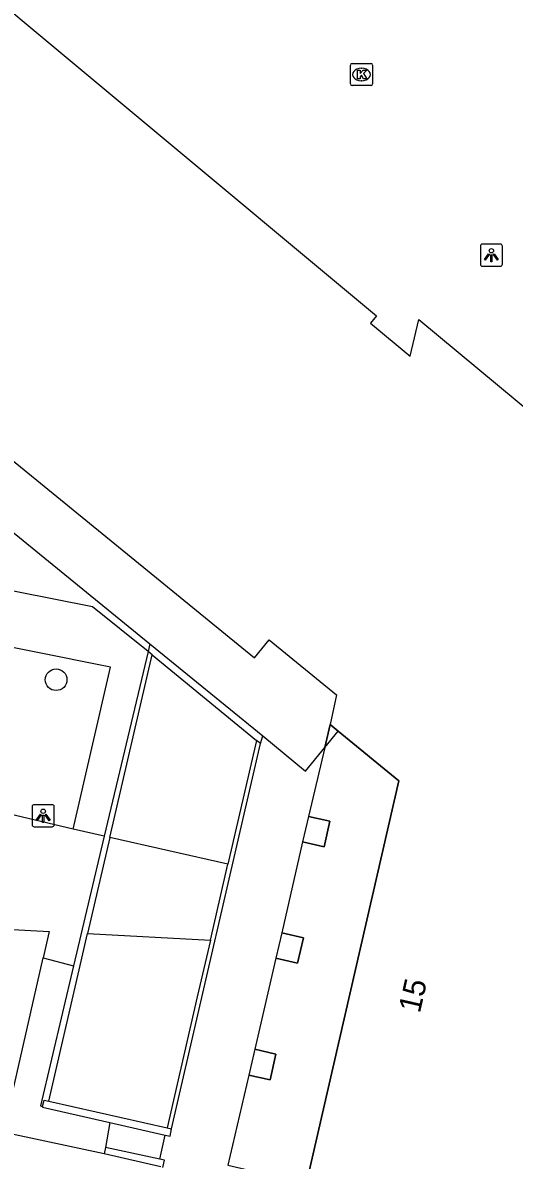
# Model space of a CAD drawing. Extents: x 161772 to 163123, y 383092 to 383917.
# Drawn here: x 161929.2 to 161951.4, y 383180.8 to 383232.1 of the extents above; entities that cross this region are included whole.
import ezdxf

# ---------------------------------------------------------------- set-up
doc = ezdxf.new("R2010")
doc.units = 0
for name, color, linetype in [('IMGEO_Boom', 7, 'Continuous'), ('IMGEO_Kolk', 7, 'Continuous'), ('IMGEO_Lichtpunt', 7, 'Continuous'), ('IMGEO_Pand', 7, 'Continuous'), ('IMGEO_Pand_nummerreeks', 7, 'Continuous'), ('IMGEO_Pand_overbouw', 7, 'Continuous'), ('IMGEO_Voetpad_gesloten', 7, 'Continuous'), ('IMGEO_Voetpad_op_trap', 7, 'Continuous'), ('IMGEO_Voetpad_open', 7, 'Continuous')]:
    doc.layers.add(name, color=color, linetype=linetype)

msp = doc.modelspace()

# ---------------------------------------------------------------- linework, layer by layer
at = {"layer": 'IMGEO_Boom'}
msp.add_circle((161930.751, 383202.465), 0.489, dxfattribs=at)
at = {"layer": 'IMGEO_Kolk'}
for p, q in [((161944.115, 383230.303), (161944.967, 383230.303)), ((161944.04, 383229.377), (161944.04, 383230.229)), ((161944.528, 383230.083), (161944.553, 383230.083)), ((161945.041, 383230.229), (161945.041, 383229.377)), ((161944.967, 383229.303), (161944.115, 383229.303)), ((161944.551, 383229.523), (161944.526, 383229.523))]:
    msp.add_line(p, q, dxfattribs=at)
for points in [[(161944.115, 383230.303), (161944.967, 383230.303)], [(161944.04, 383229.377), (161944.04, 383230.229)], [(161944.361, 383230.003), (161944.484, 383230.003), (161944.484, 383229.852), (161944.614, 383230.003), (161944.778, 383230.003), (161944.632, 383229.852), (161944.785, 383229.603), (161944.633, 383229.603), (161944.548, 383229.767), (161944.484, 383229.7), (161944.484, 383229.603), (161944.361, 383229.603), (161944.361, 383230.003)], [(161945.041, 383230.229), (161945.041, 383229.377)], [(161944.967, 383229.303), (161944.115, 383229.303)]]:
    msp.add_lwpolyline(points, dxfattribs=at)
for centre, start, end in [((161944.117, 383230.227), 91.552, 178.448), ((161944.117, 383230.227), 91.552, 178.448), ((161944.965, 383230.227), 1.552, 88.448), ((161944.965, 383230.227), 1.552, 88.448), ((161944.117, 383229.379), 181.552, 268.448), ((161944.117, 383229.379), 181.552, 268.448), ((161944.965, 383229.379), 271.552, 358.448), ((161944.965, 383229.379), 271.552, 358.448)]:
    msp.add_arc(centre, 0.0765, start, end, dxfattribs=at)
for centre, major_axis, ratio, start_param, end_param in [((161944.527, 383229.803), (-0.387, 0.002), 0.722429, 4.712389, 7.853982), ((161944.552, 383229.803), (-0.39, 0.002), 0.717154, 1.570796, 4.712389)]:
    msp.add_ellipse(centre, major_axis=major_axis, ratio=ratio, start_param=start_param, end_param=end_param, dxfattribs=at)
at = {"layer": 'IMGEO_Lichtpunt'}
for p, q in [((161950.809, 383222.141), (161950.001, 383222.141)), ((161950.809, 383222.141), (161950.001, 383222.141)), ((161949.907, 383222.046), (161949.907, 383221.239)), ((161949.907, 383222.046), (161949.907, 383221.239)), ((161950.903, 383221.239), (161950.903, 383222.046)), ((161950.903, 383221.239), (161950.903, 383222.046)), ((161950.001, 383221.145), (161950.809, 383221.145)), ((161950.001, 383221.145), (161950.809, 383221.145)), ((161929.669, 383196.724), (161929.669, 383195.917)), ((161929.669, 383196.724), (161929.669, 383195.917)), ((161930.571, 383196.819), (161929.763, 383196.819)), ((161930.571, 383196.819), (161929.763, 383196.819)), ((161930.665, 383195.917), (161930.665, 383196.724)), ((161930.665, 383195.917), (161930.665, 383196.724)), ((161929.763, 383195.823), (161930.571, 383195.823)), ((161929.763, 383195.823), (161930.571, 383195.823))]:
    msp.add_line(p, q, dxfattribs=at)
for points in [[(161950.281, 383221.71), (161950.32, 383221.682), (161950.132, 383221.42), (161950.094, 383221.447), (161950.281, 383221.71)], [(161950.383, 383221.662), (161950.43, 383221.662), (161950.43, 383221.34), (161950.383, 383221.34), (161950.383, 383221.662)], [(161950.493, 383221.682), (161950.531, 383221.709), (161950.718, 383221.447), (161950.679, 383221.419), (161950.493, 383221.682)], [(161930.043, 383196.388), (161930.082, 383196.36), (161929.894, 383196.098), (161929.856, 383196.125), (161930.043, 383196.388)], [(161930.255, 383196.36), (161930.293, 383196.387), (161930.48, 383196.125), (161930.441, 383196.097), (161930.255, 383196.36)], [(161930.145, 383196.34), (161930.192, 383196.34), (161930.192, 383196.018), (161930.145, 383196.018), (161930.145, 383196.34)]]:
    msp.add_lwpolyline(points, dxfattribs=at)
for centre in [(161950.406, 383221.844), (161930.168, 383196.522)]:
    msp.add_circle(centre, 0.0994, dxfattribs=at)
for centre, start, end in [((161950.001, 383222.046), 90, 180), ((161950.001, 383222.046), 90, 180), ((161950.809, 383222.046), 0, 90), ((161950.809, 383222.046), 0, 90), ((161950.001, 383221.239), 180, 270), ((161950.001, 383221.239), 180, 270), ((161950.809, 383221.239), 270, 0), ((161950.809, 383221.239), 270, 360), ((161929.763, 383196.724), 90, 180), ((161929.763, 383196.724), 90, 180), ((161930.571, 383196.724), 0, 90), ((161930.571, 383196.724), 0, 90), ((161929.763, 383195.917), 180, 270), ((161929.763, 383195.917), 180, 270), ((161930.571, 383195.917), 270, 0), ((161930.571, 383195.917), 270, 360)]:
    msp.add_arc(centre, 0.0946, start, end, dxfattribs=at)
at = {"layer": 'IMGEO_Pand'}
for points in [[(161917.31, 383248.385), (161919.167, 383246.891), (161915.934, 383242.925), (161915.115, 383243.559), (161905.311, 383231.535), (161939.716, 383203.459), (161940.372, 383204.262), (161943.413, 383201.779), (161943.126, 383200.444)], [(161923.685, 383236.871), (161945.217, 383218.898), (161944.945, 383218.578), (161946.743, 383217.077), (161947.136, 383218.744), (161958.77, 383209.074), (161958.947, 383208.927), (161958.917, 383207.892), (161958.785, 383207.902), (161958.465, 383206.418), (161958.386, 383206.049), (161961.28, 383205.414), (161961.604, 383206.811), (161989.958, 383183.687), (161988.555, 383177.498), (161987.599, 383177.703), (161986.982, 383174.904), (161987.902, 383174.68), (161987.617, 383173.436), (161987.088, 383171.124), (161986.569, 383168.858)], [(161943.49, 383200.144), (161946.22, 383197.897), (161942.062, 383179.735), (161941.903, 383179.773), (161941.727, 383179.058)], [(161943.126, 383200.444), (161943.49, 383200.144)], [(161941.882, 383195.142), (161942.849, 383194.919), (161943.114, 383196.069), (161942.147, 383196.292)], [(161942.147, 383196.292), (161941.882, 383195.142)], [(161940.674, 383189.884), (161941.653, 383189.659), (161941.916, 383190.806), (161940.938, 383191.031)], [(161940.938, 383191.031), (161940.674, 383189.884)], [(161939.454, 383184.607), (161940.413, 383184.387), (161940.68, 383185.551), (161939.722, 383185.771)], [(161939.722, 383185.771), (161939.454, 383184.607)]]:
    msp.add_lwpolyline(points, dxfattribs=at)
at = {"layer": 'IMGEO_Pand_overbouw'}
msp.add_lwpolyline([(161939.409, 383179.08), (161941.617, 383178.612), (161941.727, 383179.058), (161941.903, 383179.773), (161942.062, 383179.735), (161946.22, 383197.897), (161943.49, 383200.144), (161943.126, 383200.444), (161942.88, 383199.401), (161942.147, 383196.292), (161943.114, 383196.069), (161942.849, 383194.919), (161941.882, 383195.142), (161940.938, 383191.031), (161941.916, 383190.806), (161941.653, 383189.659), (161940.674, 383189.884), (161939.722, 383185.771), (161940.68, 383185.551), (161940.413, 383184.387), (161939.454, 383184.607), (161938.512, 383180.531), (161939.681, 383180.262), (161939.516, 383179.544)], close=True, dxfattribs=at)
at = {"layer": 'IMGEO_Voetpad_gesloten'}
for points in [[(161921.974, 383214.686), (161934.979, 383204.092)], [(161934.979, 383204.092), (161934.908, 383203.737)], [(161934.979, 383204.092), (161940.08, 383199.924)], [(161934.908, 383203.737), (161932.925, 383195.401)], [(161933.179, 383195.343), (161935.087, 383203.59)], [(161935.087, 383203.59), (161934.908, 383203.737)], [(161935.087, 383203.59), (161939.8, 383199.726)], [(161942.88, 383199.401), (161943.126, 383200.444)], [(161942.88, 383199.401), (161943.49, 383200.144)], [(161935.961, 383182.174), (161939.979, 383199.579)], [(161939.8, 383199.726), (161938.512, 383194.138)], [(161939.979, 383199.579), (161939.8, 383199.726)], [(161939.979, 383199.579), (161940.08, 383199.924)], [(161940.08, 383199.924), (161942.01, 383198.341), (161942.88, 383199.401)], [(161942.88, 383199.401), (161942.147, 383196.292)], [(161932.925, 383195.401), (161931.539, 383189.54)], [(161933.179, 383195.343), (161932.174, 383191)], [(161941.882, 383195.142), (161940.938, 383191.031)], [(161937.719, 383190.697), (161938.512, 383194.138)], [(161930.42, 383183.422), (161931.793, 383189.355), (161932.174, 383191)], [(161937.719, 383190.697), (161937.128, 383188.136), (161935.764, 383182.216)], [(161940.674, 383189.884), (161939.722, 383185.771)], [(161931.539, 383189.54), (161930.045, 383183.211), (161930.139, 383183.188)], [(161932.928, 383181.042), (161898.656, 383188.359)], [(161939.454, 383184.607), (161938.512, 383180.531)], [(161930.139, 383183.188), (161930.131, 383183.158), (161933.178, 383182.464)], [(161930.139, 383183.188), (161930.212, 383183.469), (161930.42, 383183.422)], [(161930.42, 383183.422), (161935.764, 383182.216)], [(161933.178, 383182.464), (161935.675, 383181.895)], [(161935.675, 383181.895), (161935.895, 383181.845), (161935.961, 383182.174)], [(161935.764, 383182.216), (161935.961, 383182.174)], [(161932.988, 383181.34), (161932.928, 383181.042)], [(161935.474, 383180.458), (161932.928, 383181.042)], [(161935.442, 383180.802), (161932.988, 383181.34)], [(161935.578, 383180.434), (161935.643, 383180.758), (161935.442, 383180.802)]]:
    msp.add_lwpolyline(points, dxfattribs=at)
at = {"layer": 'IMGEO_Voetpad_op_trap'}
for points in [[(161938.512, 383194.138), (161933.179, 383195.343)], [(161932.174, 383191), (161937.719, 383190.697)]]:
    msp.add_lwpolyline(points, dxfattribs=at)
at = {"layer": 'IMGEO_Voetpad_open'}
for points in [[(161934.908, 383203.737), (161932.393, 383205.759), (161917.042, 383208.794), (161921.974, 383214.686)], [(161931.516, 383195.707), (161933.211, 383203.037), (161915.433, 383206.604), (161910.516, 383200.666)], [(161931.516, 383195.707), (161924.643, 383197.335)], [(161906.322, 383195.46), (161900.634, 383188.537), (161928.424, 383182.206), (161930.17, 383189.903)], [(161932.925, 383195.401), (161931.516, 383195.707)], [(161923.279, 383191.486), (161930.44, 383191.095), (161930.17, 383189.903)], [(161930.17, 383189.903), (161931.539, 383189.54)], [(161933.178, 383182.464), (161932.988, 383181.34)], [(161935.442, 383180.802), (161935.675, 383181.895)]]:
    msp.add_lwpolyline(points, dxfattribs=at)

# ---------------------------------------------------------------- texts
at = {"layer": 'IMGEO_Pand_nummerreeks'}
msp.add_text('15', height=1, rotation=77.1029, dxfattribs=at).set_placement((161947.174, 383187.37))

doc.saveas('drawing.dxf')
